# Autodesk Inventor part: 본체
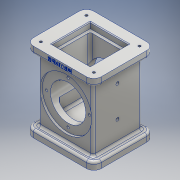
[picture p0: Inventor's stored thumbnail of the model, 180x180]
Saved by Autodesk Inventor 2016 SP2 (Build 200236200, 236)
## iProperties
Created: 2017-08
Part Number: 본체
Material: 알루미늄 6061
Document SubType Name: Modeling
Designer: Administrator
Density: 2.7 g/cm^3
Appearance: 알루미늄 - 평지
Mass: 869.098 g
Surface Area: 642.251 cm^2
Volume: 321.888 cm^3
Author: Administrator
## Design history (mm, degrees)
sketch "스케치1"
  geometry: L1 (-46, -41)-(46, -41); L2 (46, -41)-(46, 41); L3 (46, 41)-(-46, 41); L4 (-46, 41)-(-46, -41); L5 (-46, -41)-(46, 41); L6 (46, -41)-(-46, 41); 1 further point
  constraints: 12 end point, 2 midpoint, 2 parallel, 1 horizontal, 1 perpendicular
  dimensions: "d0" = 92 distance of L2.end L3.end; "d1" = 82 distance of L1.end L2.end
extrude "돌출1" new body sketch "스케치1" distance "d2" = 10; taper "d3" = 0 deg
fillet "모깎기1" dims "d4" = 10
sketch "스케치2"
  geometry: L1 (-37, -33)-(37, -33); L2 (37, -33)-(37, 33); L3 (37, 33)-(-37, 33); L4 (-37, 33)-(-37, -33); L5 (-37, -33)-(37, 33); L6 (37, -33)-(-37, 33); 1 further point
  constraints: 12 end point, 2 midpoint, 2 parallel, 1 horizontal, 1 perpendicular
  dimensions: "d5" = 74 distance of L3.end L2.end; "d6" = 66 distance of L2.end L1.end
extrude "돌출2" join sketch "스케치2" distance "d7" = 88; taper "d8" = 0 deg
sketch "스케치3"
  geometry: L1 (-46, -41)-(46, -41); L2 (46, -41)-(46, 41); L3 (46, 41)-(-46, 41); L4 (-46, 41)-(-46, -41); L5 (-46, -41)-(46, 41); L6 (46, -41)-(-46, 41); 1 further point
  constraints: 12 end point, 2 midpoint, 2 parallel, 1 horizontal, 1 perpendicular
  dimensions: "d9" = 92 distance of L3.end L2.end; "d10" = 82 distance of L2.end L1.end
extrude "돌출3" join sketch "스케치3" distance "d11" = 10; taper "d12" = 0 deg
fillet "모깎기2" dims "d13" = 10
fillet "모깎기3" dims "d14" = 3
fillet "모깎기4" dims "d15" = 3
sketch "스케치4"
  geometry: L1 (-26, -26)-(26, -26); L2 (26, -26)-(26, 26); L3 (26, 26)-(-26, 26); L4 (-26, 26)-(-26, -26); L5 (-26, -26)-(26, 26); L6 (26, -26)-(-26, 26); 1 further point
  constraints: 12 end point, 2 midpoint, 2 parallel, 1 horizontal, 1 perpendicular
  dimensions: "d16" = 52 distance of L3.end L2.end; "d17" = 52 distance of L2.end L1.end
extrude "돌출4" cut sketch "스케치4" distance "d18" = 8; taper "d19" = 0 deg
sketch "스케치5"
  geometry: L1 (24, 24)-(-24, 24); L2 (-24, 24)-(-24, -24); L3 (-24, -24)-(24, -24); L4 (24, -24)-(24, 24); L5 (24, 24)-(-24, -24); L6 (-24, 24)-(24, -24); 1 further point
  constraints: 12 end point, 2 midpoint, 2 parallel, 1 horizontal, 1 perpendicular
  dimensions: "d20" = 48 distance of L3.end L2.end; "d21" = 48 distance of L1.end L2.end
extrude "돌출5" cut sketch "스케치5" distance "d22" = 16; taper "d23" = 0 deg
sketch "스케치6"
  geometry: L1 (-22, -22)-(22, -22); L2 (22, -22)-(22, 22); L3 (22, 22)-(-22, 22); L4 (-22, 22)-(-22, -22); L5 (-22, -22)-(22, 22); L6 (22, -22)-(-22, 22); 1 further point
  constraints: 12 end point, 2 midpoint, 2 parallel, 1 horizontal, 1 perpendicular
  dimensions: "d24" = 44 distance of L3.end L2.end; "d25" = 44 distance of L2.end L1.end
extrude "돌출6" cut sketch "스케치6" distance "d26" = 74; taper "d27" = 0 deg
sketch "스케치7"
  geometry: C1 r 35 at (34, -41); 1 further point
  constraints: 1 centre point, 1 vertical alignment
  dimensions: "d28" = 70 diameter of C1; "d29" = 54 distance of point (34, -95) C1.centre
extrude "돌출7" cut sketch "스케치7" distance "d30" = 3; taper "d31" = 0 deg
fillet "모깎기5" dims "d69" = 3
fillet "모깎기6" dims "d70" = 3
fillet "모깎기7" dims "d71" = 3
sketch "스케치8"
  geometry: C1 r 35 at (0, 0) reference; C2 r 24 at (0, 0); 1 further point
  constraints: 1 centre point, 1 coincident
  dimensions: "d32" = 48 diameter of C2
extrude "돌출8" cut sketch "스케치8" stored distance "d33" = 3; taper "d34" = 0 deg
sketch "스케치9"
  geometry: L1 (95, -1)-(95, 61) reference; 4 further points
  constraints: 2 horizontal alignment, 1 midpoint
  dimensions: "d35" = 38 distance from line of point (57, 30) L1; "d36" = 42 distance of point (15, 30) point (57, 30)
hole "구멍1" sketch "스케치9" at (57, 30), (15, 30) diameter "d37" = 4.134; stored, may be unused: countersink angle "d41" = 90 deg, drill point angle "d43" = 118 deg; dims "d38" = 20, "d39" = 4, "d40" = 2, "d42" = 20
sketch "스케치10"
  geometry: L1 (0, 0)-(0, 29); A1 r 24 centre (0, 0) between (-19, -14.663) and (19, -14.663) reference; 4 further points
  constraints: 2 end point, 1 coincident, 1 vertical
  dimensions: "d44" = 29 distance of L1.start L1.end
hole "구멍2" sketch "스케치10" at (0, 29) diameter "d45" = 3.242; stored, may be unused: countersink angle "d49" = 90 deg, drill point angle "d51" = 118 deg; dims "d46" = 4, "d47" = 4, "d48" = 2, "d50" = 6
sketch "스케치11"
  geometry: A1 r 10 centre (-36, 31) between (-36, 41) and (-46, 31) reference; A2 r 10 centre (36, 31) between (46, 31) and (36, 41) reference; A3 r 10 centre (36, -31) between (36, -41) and (46, -31) reference; A4 r 10 centre (-36, -31) between (-46, -31) and (-36, -41) reference; 5 further points
  constraints: 4 coincident
hole "구멍3" sketch "스케치11" at (-36, 31), (36, 31), (36, -31), (-36, -31) diameter "d55" = 3.242; stored, may be unused: countersink angle "d59" = 90 deg, drill point angle "d61" = 118 deg; dims "d56" = 4, "d57" = 4, "d58" = 2, "d60" = 6
sketch "스케치12" dims "d13" = 10
  geometry: C1 r 1.621 at (36, -31) reference; A1 r 10 centre (-36, -31) between (-46, -31) and (-36, -41) reference; A2 r 10 centre (-36, 31) between (-36, 41) and (-46, 31) reference; A3 r 10 centre (36, 31) between (46, 31) and (36, 41) reference; 5 further points
  constraints: 4 coincident
hole "구멍4" sketch "스케치12" at (36, -31), (-36, -31), (-36, 31), (36, 31) diameter "d62" = 3.242; stored, may be unused: countersink angle "d66" = 90 deg, drill point angle "d68" = 118 deg; dims "d13" = 10, "d63" = 4, "d64" = 4, "d65" = 2, "d67" = 6
chamfer "모따기1" distance "d72" = 1; stored, may be unused: second distance "d73" = 2, angle "d74" = 45 deg
sketch "스케치13"
  geometry: L1 (-10, 0)-(-10, -7) reference; L2 (0, 0)-(72, 0) reference; 2 further points
  constraints: 1 other
  dimensions: "d75" = 46 distance from line of L1 point (36, -4); "d76" = 4 distance from line of L2 point (36, -4)
feature "엠보싱1" sketch "스케치13" dims "d0" = 92, "d1" = 82, "d77" = 0.5, "d78" = 0
node "솔리드1"
mirror "대칭1"
pattern_circular "원형 패턴1" dims angle "d53" = 360 deg
mirror "대칭2"
